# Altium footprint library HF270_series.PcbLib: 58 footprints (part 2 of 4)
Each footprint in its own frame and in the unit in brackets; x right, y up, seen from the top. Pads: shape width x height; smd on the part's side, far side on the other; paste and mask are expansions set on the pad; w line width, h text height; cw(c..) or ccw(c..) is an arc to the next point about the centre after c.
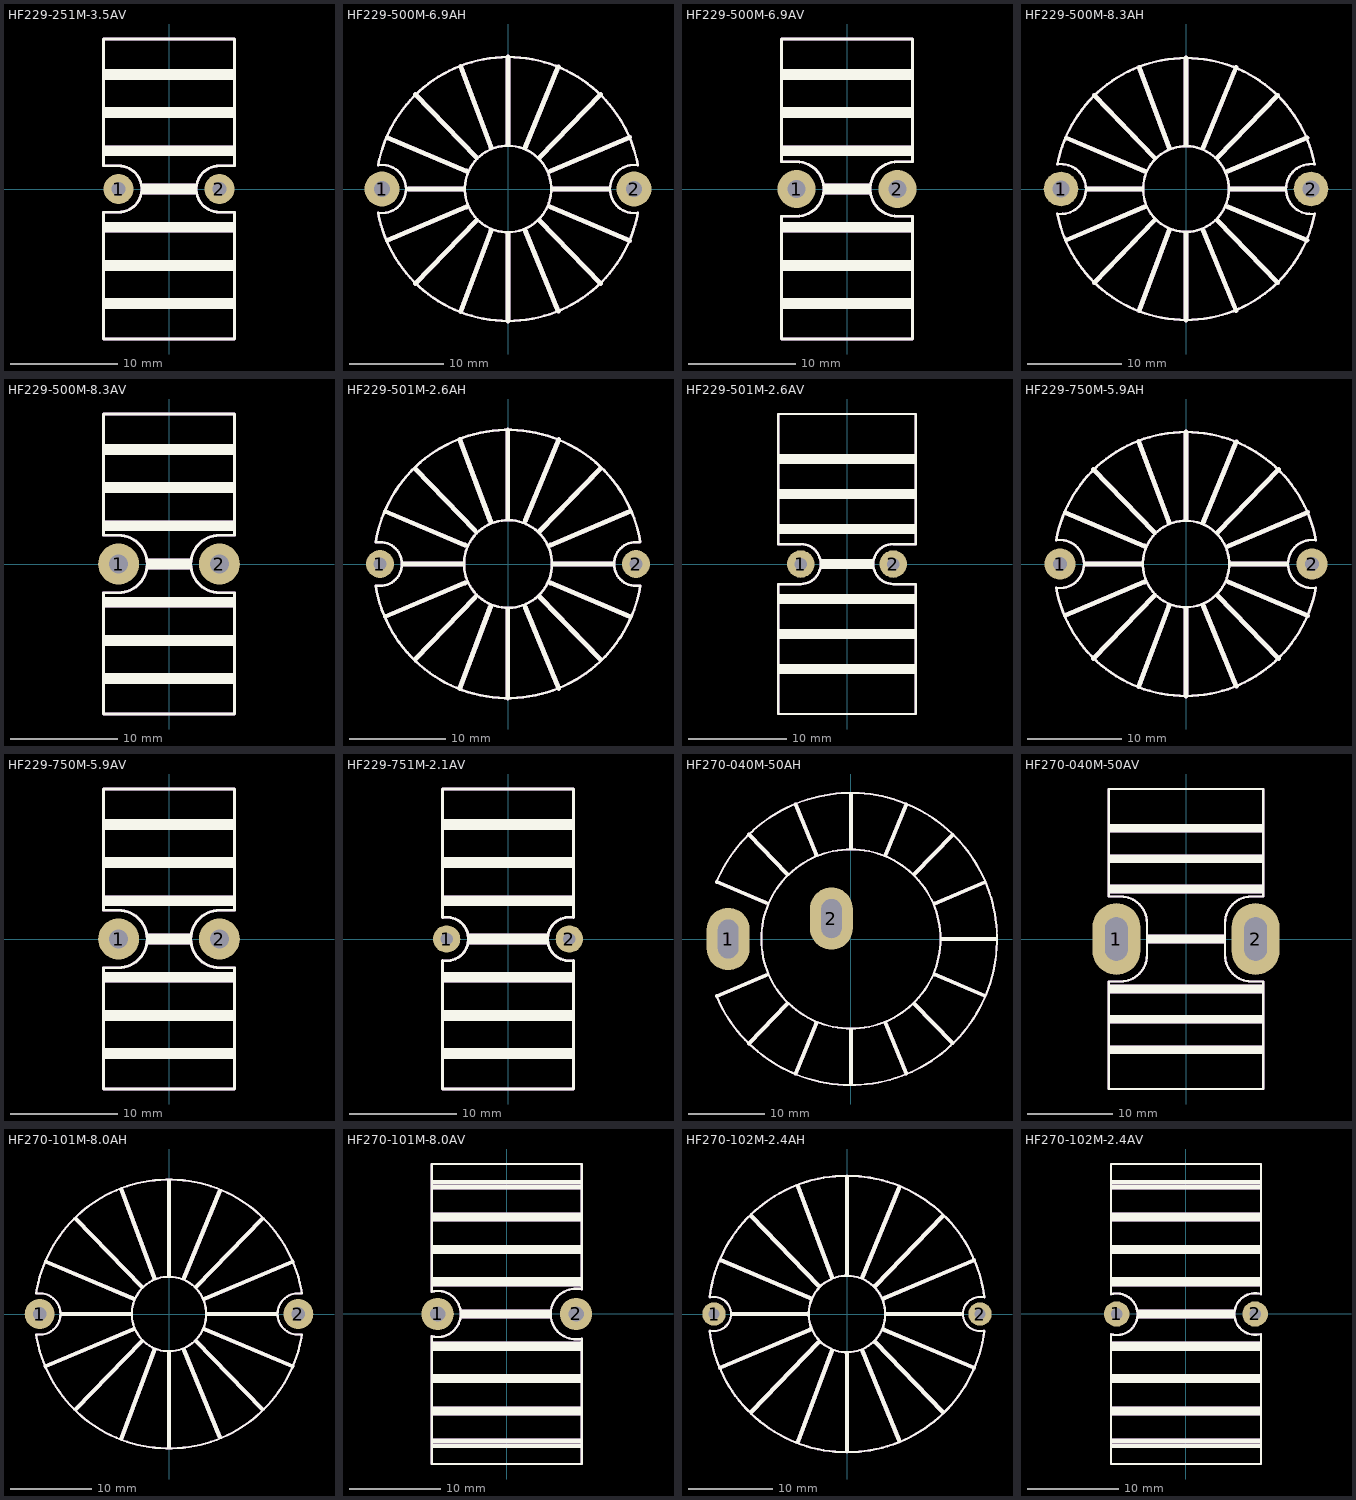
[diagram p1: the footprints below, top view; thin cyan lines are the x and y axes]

## HF229-251M-3.5AV [mil]
pads (2):
  round 110 hole 52: 1(-185,0) 2(185,0)
Top Overlay:
  lines w10: -240,-550 240,-550 240,-85 185,-85 cw(c185,0) 185,85 240,85 240,550 -240,550 -240,85 -185,85 cw(c-185,0) -185,-85 -240,-85 -240,-550
  lines w19.68: -235,-430 235,-430 ; -235,-410 235,-410 ; -235,-290 235,-290 ; -235,-270 235,-270 ; -235,-150 235,-150 ; -235,-130 235,-130 ; -235,130 235,130 ; -235,150 235,150 ; -235,270 235,270 ; -235,290 235,290 ; -235,410 235,410 ; -235,430 235,430 ; -95,-10 95,-10 ; -95,10 95,10
Mechanical 29:
  lines w10: -240,-550 240,-550 240,-85 185,-85 cw(c185,0) 185,85 240,85 240,550 -240,550 -240,85 -185,85 cw(c-185,0) -185,-85 -240,-85 -240,-550
  lines w19.68: -235,-430 235,-430 ; -235,-410 235,-410 ; -235,-290 235,-290 ; -235,-270 235,-270 ; -235,-150 235,-150 ; -235,-130 235,-130 ; -235,130 235,130 ; -235,150 235,150 ; -235,270 235,270 ; -235,290 235,290 ; -235,410 235,410 ; -235,430 235,430 ; -95,-10 95,-10 ; -95,10 95,10
  text "'.Designator'" at -800,175.15 h400

## HF229-500M-6.9AH [mil]
pads (2):
  round 145 hole 66: 1(-525,0) 2(525,0)
Top Overlay:
  circle w10: c0,0 r180
  lines w10: -540.97,-99.25 ccw(c0,0) 540.97,-99.25 ; -540.89,-98.73 ccw(c-525,0) -540.76,98.75 ; -540.9,99.63 cw(c0,0) 540.9,99.63 ; 540.76,98.75 ccw(c525,0) 540.89,-98.73
  lines w19.68: -502.44,-214.25 -173.05,-74.68 ; -502.44,214.25 -173.05,74.68 ; -415,0 -185,0 ; -385.97,-393.9 -132.7,-132.43 ; -385.97,393.9 -132.7,132.43 ; -196.89,-511.16 -70.44,-171.87 ; -196.89,511.16 -70.44,171.87 ; 0,-550 0,-185 ; 0,185 0,550 ; 72.46,-173.99 210.14,-509.94 ; 72.46,173.99 210.14,509.94 ; 132.5,-132.5 385.95,-393.93 ; 132.5,132.5 385.95,393.93 ; 175.3,-74.28 507.81,-215.17 ; 175.3,74.28 507.81,215.17 ; 185,0 420,0
Mechanical 29:
  circle w10: c0,0 r180
  lines w10: -540.97,-99.25 ccw(c0,0) 540.97,-99.25 ; -540.89,-98.73 ccw(c-525,0) -540.76,98.75 ; -540.9,99.63 cw(c0,0) 540.9,99.63 ; 540.76,98.75 ccw(c525,0) 540.89,-98.73
  lines w19.68: -502.44,-214.25 -173.05,-74.68 ; -502.44,214.25 -173.05,74.68 ; -415,0 -185,0 ; -385.97,-393.9 -132.7,-132.43 ; -385.97,393.9 -132.7,132.43 ; -196.89,-511.16 -70.44,-171.87 ; -196.89,511.16 -70.44,171.87 ; 0,-550 0,-185 ; 0,185 0,550 ; 72.46,-173.99 210.14,-509.94 ; 72.46,173.99 210.14,509.94 ; 132.5,-132.5 385.95,-393.93 ; 132.5,132.5 385.95,393.93 ; 175.3,-74.28 507.81,-215.17 ; 175.3,74.28 507.81,215.17 ; 185,0 420,0
  text "'.Designator'" at -290,145.15 h400

## HF229-500M-6.9AV [mil]
pads (2):
  round 140 hole 66: 1(-185,0) 2(185,0)
Top Overlay:
  lines w10: -240,-550 240,-550 240,-100 185,-100 cw(c185,0) 185,100 240,100 240,550 -240,550 -240,100 -185,100 cw(c-185,0) -185,-100 -240,-100 -240,-550
  lines w19.68: -235,-430 235,-430 ; -235,-410 235,-410 ; -235,-290 235,-290 ; -235,-270 235,-270 ; -235,-150 235,-150 ; -235,-130 235,-130 ; -235,130 235,130 ; -235,150 235,150 ; -235,270 235,270 ; -235,290 235,290 ; -235,410 235,410 ; -235,430 235,430 ; -80,-10 80,-10 ; -80,10 80,10
Mechanical 29:
  lines w10: -240,-550 240,-550 240,-100 185,-100 cw(c185,0) 185,100 240,100 240,550 -240,550 -240,100 -185,100 cw(c-185,0) -185,-100 -240,-100 -240,-550
  lines w19.68: -235,-430 235,-430 ; -235,-410 235,-410 ; -235,-290 235,-290 ; -235,-270 235,-270 ; -235,-150 235,-150 ; -235,-130 235,-130 ; -235,130 235,130 ; -235,150 235,150 ; -235,270 235,270 ; -235,290 235,290 ; -235,410 235,410 ; -235,430 235,430 ; -80,-10 80,-10 ; -80,10 80,10
  text "'.Designator'" at -1750,-64.85 h400

## HF229-500M-8.3AH [mil]
pads (2):
  round 145 hole 70: 1(-525,0) 2(525,0)
Top Overlay:
  circle w10: c0,0 r180
  lines w10: -540.02,104.32 cw(c0,0) 540.02,104.32 ; -538.82,104.09 cw(c-525,0) -540.1,-103.91 ccw(c0,0) 540.1,-103.91 cw(c525,0) 538.82,104.09
  lines w19.68: -502.44,-214.25 -173.05,-74.68 ; -502.44,214.25 -173.05,74.68 ; -415,0 -185,0 ; -385.97,-393.9 -132.7,-132.43 ; -385.97,393.9 -132.7,132.43 ; -196.89,-511.16 -70.44,-171.87 ; -196.89,511.16 -70.44,171.87 ; 0,-550 0,-185 ; 0,185 0,550 ; 72.46,-173.99 210.14,-509.94 ; 72.46,173.99 210.14,509.94 ; 132.5,-132.5 385.95,-393.93 ; 132.5,132.5 385.95,393.93 ; 175.3,-74.28 507.81,-215.17 ; 175.3,74.28 507.81,215.17 ; 185,0 415,0
Mechanical 29:
  circle w10: c0,0 r180
  lines w10: -540.02,104.32 cw(c0,0) 540.02,104.32 ; -538.82,104.09 cw(c-525,0) -540.1,-103.91 ccw(c0,0) 540.1,-103.91 cw(c525,0) 538.82,104.09
  lines w19.68: -502.44,-214.25 -173.05,-74.68 ; -502.44,214.25 -173.05,74.68 ; -415,0 -185,0 ; -385.97,-393.9 -132.7,-132.43 ; -385.97,393.9 -132.7,132.43 ; -196.89,-511.16 -70.44,-171.87 ; -196.89,511.16 -70.44,171.87 ; 0,-550 0,-185 ; 0,185 0,550 ; 72.46,-173.99 210.14,-509.94 ; 72.46,173.99 210.14,509.94 ; 132.5,-132.5 385.95,-393.93 ; 132.5,132.5 385.95,393.93 ; 175.3,-74.28 507.81,-215.17 ; 175.3,74.28 507.81,215.17 ; 185,0 415,0
  text "'.Designator'" at -290,145.15 h400

## HF229-500M-8.3AV [mil]
pads (2):
  round 150 hole 70: 1(-185,0) 2(185,0)
Top Overlay:
  lines w10: -240,-550 -240,-105 -185,-105 ccw(c-185,0) -185,105 -240,105 -240,550 240,550 240,105 185,105 ccw(c185,0) 185,-105 240,-105 240,-550 -240,-550
  lines w19.68: -235,-430 235,-430 ; -235,-410 235,-410 ; -235,-290 235,-290 ; -235,-270 235,-270 ; -235,-150 235,-150 ; -235,-130 235,-130 ; -235,130 235,130 ; -235,150 235,150 ; -235,270 235,270 ; -235,290 235,290 ; -235,410 235,410 ; -235,430 235,430 ; -75,-10 75,-10 ; -75,10 75,10
Mechanical 29:
  lines w10: -240,-550 -240,-105 -185,-105 ccw(c-185,0) -185,105 -240,105 -240,550 240,550 240,105 185,105 ccw(c185,0) 185,-105 240,-105 240,-550 -240,-550
  lines w19.68: -235,-430 235,-430 ; -235,-410 235,-410 ; -235,-290 235,-290 ; -235,-270 235,-270 ; -235,-150 235,-150 ; -235,-130 235,-130 ; -235,130 235,130 ; -235,150 235,150 ; -235,270 235,270 ; -235,290 235,290 ; -235,410 235,410 ; -235,430 235,430 ; -75,-10 75,-10 ; -75,10 75,10
  text "'.Designator'" at -1750,-64.85 h400

## HF229-501M-2.6AH [mil]
pads (2):
  round 115 hole 52: 1(-525,0) 2(525,0)
Top Overlay:
  circle w10: c0,0 r180
  lines w10: -542.52,90 -525,90 cw(c-525,0) -525,-90 ; -542.52,90.42 cw(c0,0) 542.52,90.42 ; -525.85,-90 -542.65,-89.61 ccw(c0,0) 542.52,-90.42 ; 520,90 540.01,90 ; 525,90 ccw(c525,0) 525,-90 542.52,-90
  lines w19.68: -501.98,-215.33 -176.61,-77.46 ; -501.98,215.33 -176.61,77.46 ; -430,0 -185,0 ; -380.22,-389.79 -134,-135.6 ; -380.22,389.79 -134,135.6 ; -197,-511.12 -71.74,-175.04 ; -197,511.12 -71.74,175.04 ; -1.31,-550 -1.31,-188.17 ; -1.31,188.17 -1.31,550 ; 71.15,-177.17 207.91,-510.86 ; 71.15,177.17 207.91,510.86 ; 131.19,-135.67 378.84,-391.12 ; 131.19,135.67 378.84,391.12 ; 174,-77.46 501.58,-216.26 ; 174,77.46 501.58,216.26 ; 185,0 430,0
Mechanical 29:
  circle w10: c0,0 r180
  lines w10: -542.52,90 -525,90 cw(c-525,0) -525,-90 ; -542.52,90.42 cw(c0,0) 542.52,90.42 ; -525.85,-90 -542.65,-89.61 ccw(c0,0) 542.52,-90.42 ; 520,90 540.01,90 ; 525,90 ccw(c525,0) 525,-90 542.52,-90
  lines w19.68: -501.98,-215.33 -176.61,-77.46 ; -501.98,215.33 -176.61,77.46 ; -430,0 -185,0 ; -380.22,-389.79 -134,-135.6 ; -380.22,389.79 -134,135.6 ; -197,-511.12 -71.74,-175.04 ; -197,511.12 -71.74,175.04 ; -1.31,-550 -1.31,-188.17 ; -1.31,188.17 -1.31,550 ; 71.15,-177.17 207.91,-510.86 ; 71.15,177.17 207.91,510.86 ; 131.19,-135.67 378.84,-391.12 ; 131.19,135.67 378.84,391.12 ; 174,-77.46 501.58,-216.26 ; 174,77.46 501.58,216.26 ; 185,0 430,0
  text "'.Designator'" at -290,145.15 h400

## HF229-501M-2.6AV [mil]
pads (2):
  round 110 hole 50: 1(-185,0) 2(185,0)
Top Overlay:
  lines w10: -275,-600 -275,-80 -185,-80 ccw(c-185,0) -185,80 -275,80 -275,600 275,600 275,80 185,80 ccw(c185,0) 185,-80 275,-80 275,-600 -275,-600
  lines w19.68: -270,-430 270,-430 ; -270,-410 270,-410 ; -270,-290 270,-290 ; -270,-270 270,-270 ; -270,-150 270,-150 ; -270,-130 270,-130 ; -270,130 270,130 ; -270,150 270,150 ; -270,270 270,270 ; -270,290 270,290 ; -270,410 270,410 ; -270,430 270,430 ; -100,-10 100,-10 ; -100,10 100,10
Mechanical 29:
  lines w10: -275,-600 -275,-80 -185,-80 ccw(c-185,0) -185,80 -275,80 -275,600 275,600 275,80 185,80 ccw(c185,0) 185,-80 275,-80 275,-600 -275,-600
  lines w19.68: -270,-430 270,-430 ; -270,-410 270,-410 ; -270,-290 270,-290 ; -270,-270 270,-270 ; -270,-150 270,-150 ; -270,-130 270,-130 ; -270,130 270,130 ; -270,150 270,150 ; -270,270 270,270 ; -270,290 270,290 ; -270,410 270,410 ; -270,430 270,430 ; -100,-10 100,-10 ; -100,10 100,10
  text "'.Designator'" at -1750,-64.85 h400

## HF229-750M-5.9AH [mil]
pads (2):
  round 130 hole 60: 1(-525,0) 2(525,0)
Top Overlay:
  circle w10: c0,0 r180
  lines w10: -541.07,-98.7 ccw(c-525,0) -541.07,98.7 cw(c0,0) 541.07,98.7 ccw(c525,0) 541.07,-98.7 cw(c0,0) -541.07,-98.7
  lines w19.68: -502.44,-214.25 -173.05,-74.68 ; -502.44,214.25 -173.05,74.68 ; -420,0 -185,0 ; -385.97,-393.9 -132.7,-132.43 ; -385.97,393.9 -132.7,132.43 ; -196.89,-511.16 -70.44,-171.87 ; -196.89,511.16 -70.44,171.87 ; 0,-550 0,-185 ; 0,185 0,550 ; 72.46,-173.99 210.14,-509.94 ; 72.46,173.99 210.14,509.94 ; 132.5,-132.5 385.95,-393.93 ; 132.5,132.5 385.95,393.93 ; 175.3,-74.28 507.81,-215.17 ; 175.3,74.28 507.81,215.17 ; 185,0 420,0
Mechanical 29:
  circle w10: c0,0 r180
  lines w10: -541.07,-98.7 ccw(c-525,0) -541.07,98.7 cw(c0,0) 541.07,98.7 ccw(c525,0) 541.07,-98.7 cw(c0,0) -541.07,-98.7
  lines w19.68: -502.44,-214.25 -173.05,-74.68 ; -502.44,214.25 -173.05,74.68 ; -420,0 -185,0 ; -385.97,-393.9 -132.7,-132.43 ; -385.97,393.9 -132.7,132.43 ; -196.89,-511.16 -70.44,-171.87 ; -196.89,511.16 -70.44,171.87 ; 0,-550 0,-185 ; 0,185 0,550 ; 72.46,-173.99 210.14,-509.94 ; 72.46,173.99 210.14,509.94 ; 132.5,-132.5 385.95,-393.93 ; 132.5,132.5 385.95,393.93 ; 175.3,-74.28 507.81,-215.17 ; 175.3,74.28 507.81,215.17 ; 185,0 420,0
  text "'.Designator'" at -290,145.15 h400

## HF229-750M-5.9AV [mil]
pads (2):
  round 150 hole 70: 1(-185,0) 2(185,0)
Top Overlay:
  lines w10: -240,-550 -240,-105 -185,-105 ccw(c-185,0) -185,105 -240,105 -240,550 240,550 240,105 185,105 ccw(c185,0) 185,-105 240,-105 240,-550 -240,-550
  lines w19.68: -235,-430 235,-430 ; -235,-410 235,-410 ; -235,-290 235,-290 ; -235,-270 235,-270 ; -235,-150 235,-150 ; -235,-130 235,-130 ; -235,130 235,130 ; -235,150 235,150 ; -235,270 235,270 ; -235,290 235,290 ; -235,410 235,410 ; -235,430 235,430 ; -75,-10 75,-10 ; -75,10 75,10
Mechanical 29:
  lines w10: -240,-550 -240,-105 -185,-105 ccw(c-185,0) -185,105 -240,105 -240,550 240,550 240,105 185,105 ccw(c185,0) 185,-105 240,-105 240,-550 -240,-550
  lines w19.68: -235,-430 235,-430 ; -235,-410 235,-410 ; -235,-290 235,-290 ; -235,-270 235,-270 ; -235,-150 235,-150 ; -235,-130 235,-130 ; -235,130 235,130 ; -235,150 235,150 ; -235,270 235,270 ; -235,290 235,290 ; -235,410 235,410 ; -235,430 235,430 ; -75,-10 75,-10 ; -75,10 75,10
  text "'.Designator'" at -1750,-64.85 h400

## HF229-751M-2.1AV [mil]
pads (2):
  round 100 hole 45: 1(-225,0) 2(225,0)
Top Overlay:
  lines w10: -240,80 -240,550 240,550 240,78.58 ccw(c225,0) 240,-78.58 240,-550 -240,-550 -240,-78.58 ccw(c-225,0) -239.74,78.63
  lines w19.68: -235,-430 235,-430 ; -235,-410 235,-410 ; -235,-290 235,-290 ; -235,-270 235,-270 ; -235,-150 235,-150 ; -235,-130 235,-130 ; -235,130 235,130 ; -235,150 235,150 ; -235,270 235,270 ; -235,290 235,290 ; -235,410 235,410 ; -235,430 235,430 ; -140,-10 140,-10 ; -140,10 140,10
Mechanical 29:
  lines w10: -240,80 -240,550 240,550 240,78.58 ccw(c225,0) 240,-78.58 240,-550 -240,-550 -240,-78.58 ccw(c-225,0) -239.74,78.63
  lines w19.68: -235,-430 235,-430 ; -235,-410 235,-410 ; -235,-290 235,-290 ; -235,-270 235,-270 ; -235,-150 235,-150 ; -235,-130 235,-130 ; -235,130 235,130 ; -235,150 235,150 ; -235,270 235,270 ; -235,290 235,290 ; -235,410 235,410 ; -235,430 235,430 ; -140,-10 140,-10 ; -140,10 140,10
  text "'.Designator'" at -1750,-64.85 h400

## HF270-040M-50AH [mil]
pads (2):
  oval 220x320 hole 105 slot 200 at 90 deg: 1(-630,0) 2(-100,105)
Top Overlay:
  circle w10: c0,0 r460
  lines w10: -690.08,-293.76 ccw(c0,0) 737.69,-135.35 ccw(c0,0) -690.08,293.76
  lines w19.68: -688.66,-293.16 -435.19,-185.75 ; -688.66,293.16 -435.19,185.75 ; -523.79,-536.17 -327.02,-333.04 ; -523.79,536.17 -327.02,333.04 ; -284.09,-690.37 -178.79,-433.45 ; -284.09,690.37 -178.79,433.45 ; 0,-745 0,-470 ; 0,470 0,745 ; 178.79,-433.45 284.09,-690.37 ; 178.79,433.45 284.09,690.37 ; 326.97,-333.09 521.4,-533.65 ; 326.97,333.09 521.4,533.65 ; 429.21,-181.87 686.7,-290.98 ; 429.21,181.87 686.7,290.98 ; 465,0 745,0
Mechanical 29:
  circle w10: c0,0 r460
  lines w10: -690.08,-293.76 ccw(c0,0) 737.69,-135.35 ccw(c0,0) -690.08,293.76
  lines w19.68: -688.66,-293.16 -435.19,-185.75 ; -688.66,293.16 -435.19,185.75 ; -523.79,-536.17 -327.02,-333.04 ; -523.79,536.17 -327.02,333.04 ; -284.09,-690.37 -178.79,-433.45 ; -284.09,690.37 -178.79,433.45 ; 0,-745 0,-470 ; 0,470 0,745 ; 178.79,-433.45 284.09,-690.37 ; 178.79,433.45 284.09,690.37 ; 326.97,-333.09 521.4,-533.65 ; 326.97,333.09 521.4,533.65 ; 429.21,-181.87 686.7,-290.98 ; 429.21,181.87 686.7,290.98 ; 465,0 745,0
  text "'.Designator'" at -290,145.15 h400

## HF270-040M-50AV [mil]
pads (2):
  oval 220x330 hole 105 slot 200 at 90 deg: 1(-320,0) 2(320,0)
Top Overlay:
  lines w10: -355,-690 -355,-215 -355,-195 -300,-195 ccw(c-300,-75) -180,-75 -180,0 -180,75 ccw(c-300,75) -300,195 -355,195 -355,215 -355,690 355,690 355,215 355,195 300,195 ccw(c300,75) 180,75 180,0 180,-75 ccw(c300,-75) 300,-195 355,-195 355,-215 355,-690 -355,-690
  lines w19.68: -350,-520 350,-520 ; -350,-500 350,-500 ; -350,-380 350,-380 ; -350,-360 350,-360 ; -350,-240 350,-240 ; -350,-220 350,-220 ; -350,220 350,220 ; -350,240 350,240 ; -350,360 350,360 ; -350,380 350,380 ; -350,500 350,500 ; -350,520 350,520 ; -175,-10 175,-10 ; -175,10 175,10
Mechanical 29:
  lines w10: -355,-690 -355,-215 -355,-195 -300,-195 ccw(c-300,-75) -180,-75 -180,0 -180,75 ccw(c-300,75) -300,195 -355,195 -355,215 -355,690 355,690 355,215 355,195 300,195 ccw(c300,75) 180,75 180,0 180,-75 ccw(c300,-75) 300,-195 355,-195 355,-215 355,-690 -355,-690
  lines w19.68: -350,-520 350,-520 ; -350,-500 350,-500 ; -350,-380 350,-380 ; -350,-360 350,-360 ; -350,-240 350,-240 ; -350,-220 350,-220 ; -350,220 350,220 ; -350,240 350,240 ; -350,360 350,360 ; -350,380 350,380 ; -350,500 350,500 ; -350,520 350,520 ; -175,-10 175,-10 ; -175,10 175,10
  text "'.Designator'" at -375,185.15 h400

## HF270-101M-8.0AH [mil]
pads (2):
  round 145 hole 67: 1(-625,0) 2(625,0)
Top Overlay:
  circle w10: c0,0 r180
  lines w10: -642.5,-98.46 ccw(c0,0) 642.5,-98.46 cw(c625,0) 642.5,98.46 ccw(c0,0) -642.5,98.46 cw(c-625,0) -642.5,-98.46
  lines w19.68: -596.03,-252.56 -175.3,-74.28 ; -593.79,252.95 -173.05,74.68 ; -520,0 -185,0 ; -450,-460 -132.7,-132.43 ; -450,460 -132.7,132.43 ; -230,-600 -70.44,-171.87 ; -230,600 -70.44,171.87 ; 0,-640 0,-185 ; 0,185 0,640 ; 72.46,-173.99 243.97,-592.47 ; 72.46,173.99 243.97,592.47 ; 132.5,-132.5 450,-460 ; 132.5,132.5 450,460 ; 175.3,-74.28 596.03,-252.56 ; 175.3,74.28 596.03,252.56 ; 185,0 520,0
Mechanical 29:
  circle w10: c0,0 r180
  lines w10: -642.5,-98.46 ccw(c0,0) 642.5,-98.46 cw(c625,0) 642.5,98.46 ccw(c0,0) -642.5,98.46 cw(c-625,0) -642.5,-98.46
  lines w19.68: -596.03,-252.56 -175.3,-74.28 ; -593.79,252.95 -173.05,74.68 ; -520,0 -185,0 ; -450,-460 -132.7,-132.43 ; -450,460 -132.7,132.43 ; -230,-600 -70.44,-171.87 ; -230,600 -70.44,171.87 ; 0,-640 0,-185 ; 0,185 0,640 ; 72.46,-173.99 243.97,-592.47 ; 72.46,173.99 243.97,592.47 ; 132.5,-132.5 450,-460 ; 132.5,132.5 450,460 ; 175.3,-74.28 596.03,-252.56 ; 175.3,74.28 596.03,252.56 ; 185,0 520,0
  text "'.Designator'" at -290,145.15 h400

## HF270-101M-8.0AV [mil]
pads (2):
  round 140 hole 67: 1(-300,0) 2(300,0)
Top Overlay:
  lines w10: 325,106.51 325,650 -325,650 -325,96.82 cw(c-300,0) -325,-96.82 -325,-650 325,-650 325,-107.12 cw(c300,0) 325,107.12
  lines w19.68: -320,-570 320,-570 ; -320,-550 320,-550 ; -320,-430 320,-430 ; -320,-410 320,-410 ; -320,-290 320,-290 ; -320,-270 320,-270 ; -320,-150 320,-150 ; -320,-130 320,-130 ; -320,130 320,130 ; -320,150 320,150 ; -320,270 320,270 ; -320,290 320,290 ; -320,410 320,410 ; -320,430 320,430 ; -320,550 320,550 ; -320,570 320,570 ; -195,-10 185,-10 ; -195,10 185,10
Mechanical 29:
  lines w10: 325,106.51 325,650 -325,650 -325,96.82 cw(c-300,0) -325,-96.82 -325,-650 325,-650 325,-107.12 cw(c300,0) 325,107.12
  lines w19.68: -320,-570 320,-570 ; -320,-550 320,-550 ; -320,-430 320,-430 ; -320,-410 320,-410 ; -320,-290 320,-290 ; -320,-270 320,-270 ; -320,-150 320,-150 ; -320,-130 320,-130 ; -320,130 320,130 ; -320,150 320,150 ; -320,270 320,270 ; -320,290 320,290 ; -320,410 320,410 ; -320,430 320,430 ; -320,550 320,550 ; -320,570 320,570 ; -195,-10 185,-10 ; -195,10 185,10
  text "'.Designator'" at -1750,-64.85 h400

## HF270-102M-2.4AH [mil]
pads (2):
  round 110 hole 50: 1(-625,0) 2(625,0)
Top Overlay:
  circle w10: c0,0 r180
  lines w10: -644.98,-80.62 ccw(c0,0) 645.06,-80.01 ; -644.9,81.25 cw(c0,0) 644.98,80.62 ; -644.4,-77.61 ccw(c-625,0) -644.4,77.61 ; 644.4,-77.61 cw(c625,0) 645.61,77.3
  lines w19.68: -596.03,-252.56 -175.3,-74.28 ; -593.79,252.95 -173.05,74.68 ; -540,0 -185,0 ; -450,-460 -132.7,-132.43 ; -450,460 -132.7,132.43 ; -230,-600 -70.44,-171.87 ; -230,600 -70.44,171.87 ; 0,-640 0,-185 ; 0,185 0,640 ; 72.46,-173.99 243.97,-592.47 ; 72.46,173.99 243.97,592.47 ; 132.5,-132.5 450,-460 ; 132.5,132.5 450,460 ; 175.3,-74.28 596.03,-252.56 ; 175.3,74.28 596.03,252.56 ; 185,0 535,0
Mechanical 29:
  circle w10: c0,0 r180
  lines w10: -644.98,-80.62 ccw(c0,0) 645.06,-80.01 ; -644.9,81.25 cw(c0,0) 644.98,80.62 ; -644.4,-77.61 ccw(c-625,0) -644.4,77.61 ; 644.4,-77.61 cw(c625,0) 645.61,77.3
  lines w19.68: -596.03,-252.56 -175.3,-74.28 ; -593.79,252.95 -173.05,74.68 ; -540,0 -185,0 ; -450,-460 -132.7,-132.43 ; -450,460 -132.7,132.43 ; -230,-600 -70.44,-171.87 ; -230,600 -70.44,171.87 ; 0,-640 0,-185 ; 0,185 0,640 ; 72.46,-173.99 243.97,-592.47 ; 72.46,173.99 243.97,592.47 ; 132.5,-132.5 450,-460 ; 132.5,132.5 450,460 ; 175.3,-74.28 596.03,-252.56 ; 175.3,74.28 596.03,252.56 ; 185,0 535,0
  text "'.Designator'" at -290,145.15 h400

## HF270-102M-2.4AV [mil]
pads (2):
  round 110 hole 50: 1(-300,0) 2(300,0)
Top Overlay:
  lines w10: -325,-87.71 ccw(c-299.6,-1.37) -325,84.97 ; -325,-86.86 -325,-650 325,-650 325,-86.46 cw(c300,0) 325,86.46 ; -325,84.12 -325,650 325,650 325,85.49
  lines w19.68: -320,-570 320,-570 ; -320,-550 320,-550 ; -320,-430 320,-430 ; -320,-410 320,-410 ; -320,-290 320,-290 ; -320,-270 320,-270 ; -320,-150 320,-150 ; -320,-130 320,-130 ; -320,130 320,130 ; -320,150 320,150 ; -320,270 320,270 ; -320,290 320,290 ; -320,410 320,410 ; -320,430 320,430 ; -320,550 320,550 ; -320,570 320,570 ; -205,-10 205,-10 ; -205,10 205,10
Mechanical 29:
  lines w10: -325,-87.71 ccw(c-299.6,-1.37) -325,84.97 ; -325,-86.86 -325,-650 325,-650 325,-86.46 cw(c300,0) 325,86.46 ; -325,84.12 -325,650 325,650 325,85.49
  lines w19.68: -320,-570 320,-570 ; -320,-550 320,-550 ; -320,-430 320,-430 ; -320,-410 320,-410 ; -320,-290 320,-290 ; -320,-270 320,-270 ; -320,-150 320,-150 ; -320,-130 320,-130 ; -320,130 320,130 ; -320,150 320,150 ; -320,270 320,270 ; -320,290 320,290 ; -320,410 320,410 ; -320,430 320,430 ; -320,550 320,550 ; -320,570 320,570 ; -205,-10 205,-10 ; -205,10 205,10
  text "'.Designator'" at -1750,-64.85 h400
